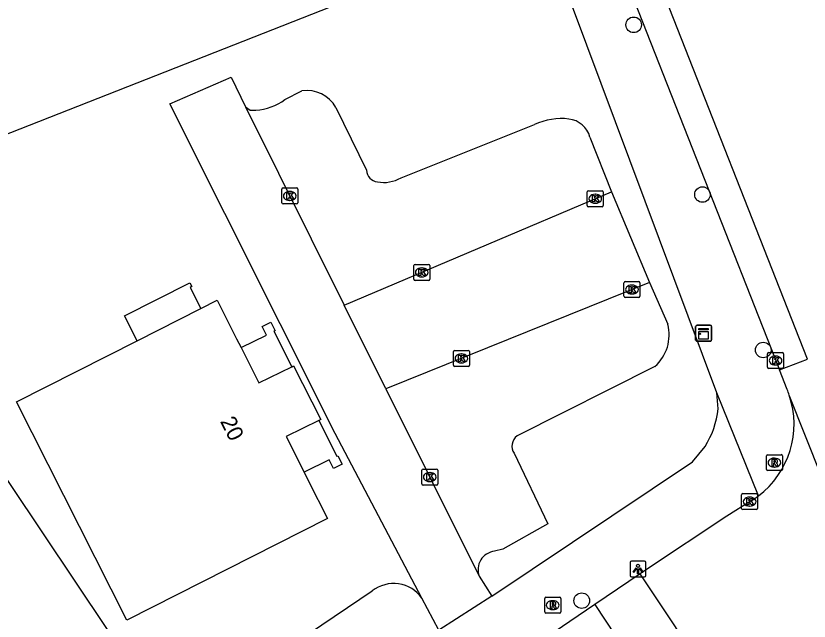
# Model space of a CAD drawing. Extents: x 161087 to 161922, y 382574 to 383873.
# Drawn here: x 161691.15 to 161740.93, y 382709.04 to 382747.01 of the extents above; entities that cross this region are included whole.
import ezdxf

# ---------------------------------------------------------------- set-up
doc = ezdxf.new("R2010")
doc.units = 0
for name, color, linetype in [('IMGEO_Boom', 7, 'Continuous'), ('IMGEO_Kast', 7, 'Continuous'), ('IMGEO_Kolk', 7, 'Continuous'), ('IMGEO_Lichtpunt', 7, 'Continuous'), ('IMGEO_Pand', 7, 'Continuous'), ('IMGEO_Pand_nummerreeks', 7, 'Continuous'), ('IMGEO_Parkeervlak_open', 7, 'Continuous'), ('IMGEO_Rijbaan_lokaal_open', 7, 'Continuous'), ('IMGEO_Rioolput', 7, 'Continuous'), ('IMGEO_Voetpad_op_trap', 7, 'Continuous'), ('IMGEO_Voetpad_open', 7, 'Continuous')]:
    doc.layers.add(name, color=color, linetype=linetype)

msp = doc.modelspace()

# ---------------------------------------------------------------- linework, layer by layer
at = {"layer": 'IMGEO_Boom'}
for centre in [(161729.923, 382746.451), (161734.24, 382735.804), (161738.053, 382726.048), (161726.662, 382710.319)]:
    msp.add_circle(centre, 0.489, dxfattribs=at)
at = {"layer": 'IMGEO_Kast'}
for p, q in [((161733.813, 382726.675), (161733.813, 382727.516)), ((161733.813, 382727.516), (161733.813, 382726.675)), ((161733.888, 382727.6), (161734.729, 382727.6)), ((161734.729, 382727.6), (161733.888, 382727.6)), ((161734.813, 382727.525), (161734.813, 382726.684)), ((161734.813, 382726.684), (161734.813, 382727.525)), ((161734.738, 382726.6), (161733.897, 382726.6)), ((161733.897, 382726.6), (161734.738, 382726.6))]:
    msp.add_line(p, q, dxfattribs=at)
for points in [[(161734.008, 382727.39), (161734.608, 382727.39), (161734.608, 382727.305), (161734.008, 382727.305), (161734.008, 382727.39)], [(161734.008, 382727.215), (161734.608, 382727.215), (161734.608, 382726.726), (161734.008, 382726.726), (161734.008, 382727.215)]]:
    msp.add_lwpolyline(points, dxfattribs=at)
msp.add_circle((161734.092, 382727.064), 0.0377, dxfattribs=at)
for centre, start, end in [((161733.891, 382727.522), 92.4484, 184.2845), ((161733.891, 382727.522), 92.4484, 184.2845), ((161734.735, 382727.522), 2.4484, 94.2845), ((161734.735, 382727.522), 2.4484, 94.2845), ((161733.891, 382726.678), 182.4484, 274.2845), ((161733.891, 382726.678), 182.4484, 274.2845), ((161734.735, 382726.678), 272.4484, 4.2845), ((161734.735, 382726.678), 272.4484, 4.2845)]:
    msp.add_arc(centre, 0.0779, start, end, dxfattribs=at)
at = {"layer": 'IMGEO_Kolk'}
for p, q in [((161707.915, 382736.214), (161708.767, 382736.214)), ((161707.84, 382735.288), (161707.84, 382736.14)), ((161708.328, 382735.994), (161708.353, 382735.994)), ((161708.841, 382736.14), (161708.841, 382735.288)), ((161727.01, 382735.111), (161727.01, 382735.963)), ((161727.085, 382736.037), (161727.937, 382736.037)), ((161727.498, 382735.817), (161727.523, 382735.817)), ((161728.011, 382735.963), (161728.011, 382735.111)), ((161708.767, 382735.214), (161707.915, 382735.214)), ((161708.351, 382735.434), (161708.326, 382735.434)), ((161727.521, 382735.257), (161727.496, 382735.257)), ((161727.937, 382735.037), (161727.085, 382735.037)), ((161716.125, 382730.492), (161716.125, 382731.344)), ((161716.2, 382731.418), (161717.052, 382731.418)), ((161716.613, 382731.198), (161716.638, 382731.198)), ((161717.126, 382731.344), (161717.126, 382730.492)), ((161717.052, 382730.418), (161716.2, 382730.418)), ((161716.636, 382730.638), (161716.611, 382730.638)), ((161729.315, 382729.417), (161729.315, 382730.269)), ((161729.39, 382730.343), (161730.242, 382730.343)), ((161730.316, 382730.269), (161730.316, 382729.417)), ((161729.803, 382730.123), (161729.828, 382730.123)), ((161730.242, 382729.343), (161729.39, 382729.343)), ((161729.826, 382729.563), (161729.801, 382729.563)), ((161718.61, 382725.093), (161718.61, 382725.945)), ((161718.685, 382726.019), (161719.537, 382726.019)), ((161719.098, 382725.799), (161719.123, 382725.799)), ((161719.611, 382725.945), (161719.611, 382725.093)), ((161738.328, 382724.961), (161738.328, 382725.813)), ((161738.403, 382725.887), (161739.255, 382725.887)), ((161739.329, 382725.813), (161739.329, 382724.961)), ((161719.121, 382725.239), (161719.096, 382725.239)), ((161738.816, 382725.667), (161738.841, 382725.667)), ((161719.537, 382725.019), (161718.685, 382725.019)), ((161739.255, 382724.887), (161738.403, 382724.887)), ((161738.839, 382725.107), (161738.814, 382725.107)), ((161716.627, 382717.65), (161716.627, 382718.502)), ((161716.702, 382718.576), (161717.554, 382718.576)), ((161717.115, 382718.356), (161717.14, 382718.356)), ((161717.628, 382718.502), (161717.628, 382717.65)), ((161717.138, 382717.796), (161717.113, 382717.796)), ((161717.554, 382717.576), (161716.702, 382717.576)), ((161736.698, 382716.109), (161736.698, 382716.961)), ((161736.773, 382717.035), (161737.625, 382717.035)), ((161737.186, 382716.815), (161737.211, 382716.815)), ((161737.699, 382716.961), (161737.699, 382716.109)), ((161737.209, 382716.255), (161737.184, 382716.255)), ((161737.625, 382716.035), (161736.773, 382716.035))]:
    msp.add_line(p, q, dxfattribs=at)
for points in [[(161707.915, 382736.214), (161708.767, 382736.214)], [(161707.84, 382735.288), (161707.84, 382736.14)], [(161708.161, 382735.914), (161708.284, 382735.914), (161708.284, 382735.763), (161708.414, 382735.914), (161708.578, 382735.914), (161708.432, 382735.763), (161708.585, 382735.514), (161708.433, 382735.514), (161708.348, 382735.678), (161708.284, 382735.611), (161708.284, 382735.514), (161708.161, 382735.514), (161708.161, 382735.914)], [(161708.841, 382736.14), (161708.841, 382735.288)], [(161727.01, 382735.111), (161727.01, 382735.963)], [(161727.085, 382736.037), (161727.937, 382736.037)], [(161727.331, 382735.737), (161727.454, 382735.737), (161727.454, 382735.586), (161727.584, 382735.737), (161727.748, 382735.737), (161727.602, 382735.586), (161727.755, 382735.337), (161727.603, 382735.337), (161727.518, 382735.501), (161727.454, 382735.434), (161727.454, 382735.337), (161727.331, 382735.337), (161727.331, 382735.737)], [(161728.011, 382735.963), (161728.011, 382735.111)], [(161708.767, 382735.214), (161707.915, 382735.214)], [(161727.937, 382735.037), (161727.085, 382735.037)], [(161716.125, 382730.492), (161716.125, 382731.344)], [(161716.2, 382731.418), (161717.052, 382731.418)], [(161717.126, 382731.344), (161717.126, 382730.492)], [(161716.446, 382731.118), (161716.569, 382731.118), (161716.569, 382730.967), (161716.699, 382731.118), (161716.863, 382731.118), (161716.717, 382730.967), (161716.87, 382730.718), (161716.718, 382730.718), (161716.633, 382730.882), (161716.569, 382730.815), (161716.569, 382730.718), (161716.446, 382730.718), (161716.446, 382731.118)], [(161717.052, 382730.418), (161716.2, 382730.418)], [(161729.315, 382729.417), (161729.315, 382730.269)], [(161729.39, 382730.343), (161730.242, 382730.343)], [(161730.316, 382730.269), (161730.316, 382729.417)], [(161729.636, 382730.043), (161729.759, 382730.043), (161729.759, 382729.892), (161729.889, 382730.043), (161730.053, 382730.043), (161729.907, 382729.892), (161730.06, 382729.643), (161729.908, 382729.643), (161729.823, 382729.807), (161729.759, 382729.74), (161729.759, 382729.643), (161729.636, 382729.643), (161729.636, 382730.043)], [(161730.242, 382729.343), (161729.39, 382729.343)], [(161718.61, 382725.093), (161718.61, 382725.945)], [(161718.685, 382726.019), (161719.537, 382726.019)], [(161718.931, 382725.719), (161719.054, 382725.719), (161719.054, 382725.568), (161719.184, 382725.719), (161719.348, 382725.719), (161719.202, 382725.568), (161719.355, 382725.319), (161719.203, 382725.319), (161719.118, 382725.483), (161719.054, 382725.416), (161719.054, 382725.319), (161718.931, 382725.319), (161718.931, 382725.719)], [(161719.611, 382725.945), (161719.611, 382725.093)], [(161738.328, 382724.961), (161738.328, 382725.813)], [(161738.403, 382725.887), (161739.255, 382725.887)], [(161739.329, 382725.813), (161739.329, 382724.961)], [(161738.649, 382725.587), (161738.772, 382725.587), (161738.772, 382725.436), (161738.902, 382725.587), (161739.066, 382725.587), (161738.92, 382725.436), (161739.073, 382725.187), (161738.921, 382725.187), (161738.836, 382725.351), (161738.772, 382725.284), (161738.772, 382725.187), (161738.649, 382725.187), (161738.649, 382725.587)], [(161719.537, 382725.019), (161718.685, 382725.019)], [(161739.255, 382724.887), (161738.403, 382724.887)], [(161716.627, 382717.65), (161716.627, 382718.502)], [(161716.702, 382718.576), (161717.554, 382718.576)], [(161716.948, 382718.276), (161717.071, 382718.276), (161717.071, 382718.125), (161717.201, 382718.276), (161717.365, 382718.276), (161717.219, 382718.125), (161717.372, 382717.876), (161717.22, 382717.876), (161717.135, 382718.04), (161717.071, 382717.973), (161717.071, 382717.876), (161716.948, 382717.876), (161716.948, 382718.276)], [(161717.628, 382718.502), (161717.628, 382717.65)], [(161717.554, 382717.576), (161716.702, 382717.576)], [(161736.698, 382716.109), (161736.698, 382716.961)], [(161736.773, 382717.035), (161737.625, 382717.035)], [(161737.699, 382716.961), (161737.699, 382716.109)], [(161737.019, 382716.735), (161737.142, 382716.735), (161737.142, 382716.584), (161737.272, 382716.735), (161737.436, 382716.735), (161737.29, 382716.584), (161737.443, 382716.335), (161737.291, 382716.335), (161737.206, 382716.499), (161737.142, 382716.432), (161737.142, 382716.335), (161737.019, 382716.335), (161737.019, 382716.735)], [(161737.625, 382716.035), (161736.773, 382716.035)]]:
    msp.add_lwpolyline(points, dxfattribs=at)
for centre, start, end in [((161707.917, 382736.138), 91.552, 178.448), ((161707.917, 382736.138), 91.552, 178.448), ((161708.765, 382736.138), 1.552, 88.448), ((161708.765, 382736.138), 1.552, 88.448), ((161727.087, 382735.961), 91.552, 178.448), ((161727.087, 382735.961), 91.552, 178.448), ((161727.935, 382735.961), 1.552, 88.448), ((161727.935, 382735.961), 1.552, 88.448), ((161707.917, 382735.29), 181.552, 268.448), ((161707.917, 382735.29), 181.552, 268.448), ((161708.765, 382735.29), 271.552, 358.448), ((161708.765, 382735.29), 271.552, 358.448), ((161727.087, 382735.113), 181.552, 268.448), ((161727.087, 382735.113), 181.552, 268.448), ((161727.935, 382735.113), 271.552, 358.448), ((161727.935, 382735.113), 271.552, 358.448), ((161716.202, 382731.342), 91.552, 178.448), ((161716.202, 382731.342), 91.552, 178.448), ((161717.05, 382731.342), 1.552, 88.448), ((161717.05, 382731.342), 1.552, 88.448), ((161716.202, 382730.494), 181.552, 268.448), ((161716.202, 382730.494), 181.552, 268.448), ((161717.05, 382730.494), 271.552, 358.448), ((161717.05, 382730.494), 271.552, 358.448), ((161729.392, 382730.267), 91.552, 178.448), ((161729.392, 382730.267), 91.552, 178.448), ((161730.24, 382730.267), 1.552, 88.448), ((161730.24, 382730.267), 1.552, 88.448), ((161729.392, 382729.419), 181.552, 268.448), ((161729.392, 382729.419), 181.552, 268.448), ((161730.24, 382729.419), 271.552, 358.448), ((161730.24, 382729.419), 271.552, 358.448), ((161718.687, 382725.943), 91.552, 178.448), ((161718.687, 382725.943), 91.552, 178.448), ((161719.535, 382725.943), 1.552, 88.448), ((161719.535, 382725.943), 1.552, 88.448), ((161738.405, 382725.811), 91.552, 178.448), ((161738.405, 382725.811), 91.552, 178.448), ((161739.253, 382725.811), 1.552, 88.448), ((161739.253, 382725.811), 1.552, 88.448), ((161718.687, 382725.095), 181.552, 268.448), ((161718.687, 382725.095), 181.552, 268.448), ((161719.535, 382725.095), 271.552, 358.448), ((161719.535, 382725.095), 271.552, 358.448), ((161738.405, 382724.963), 181.552, 268.448), ((161738.405, 382724.963), 181.552, 268.448), ((161739.253, 382724.963), 271.552, 358.448), ((161739.253, 382724.963), 271.552, 358.448), ((161716.704, 382718.5), 91.552, 178.448), ((161716.704, 382718.5), 91.552, 178.448), ((161717.552, 382718.5), 1.552, 88.448), ((161717.552, 382718.5), 1.552, 88.448), ((161716.704, 382717.652), 181.552, 268.448), ((161716.704, 382717.652), 181.552, 268.448), ((161717.552, 382717.652), 271.552, 358.448), ((161717.552, 382717.652), 271.552, 358.448), ((161736.775, 382716.959), 91.552, 178.448), ((161736.775, 382716.959), 91.552, 178.448), ((161737.623, 382716.959), 1.552, 88.448), ((161737.623, 382716.959), 1.552, 88.448), ((161736.775, 382716.111), 181.552, 268.448), ((161736.775, 382716.111), 181.552, 268.448), ((161737.623, 382716.111), 271.552, 358.448), ((161737.623, 382716.111), 271.552, 358.448)]:
    msp.add_arc(centre, 0.0765, start, end, dxfattribs=at)
for centre, major_axis, ratio, start_param, end_param in [((161708.327, 382735.714), (-0.387, 0.002), 0.722429, 4.712389, 7.853982), ((161708.352, 382735.714), (-0.39, 0.002), 0.717154, 1.570796, 4.712389), ((161727.497, 382735.537), (-0.387, 0.002), 0.722429, 4.712389, 7.853982), ((161727.522, 382735.537), (-0.39, 0.002), 0.717154, 1.570796, 4.712389), ((161716.612, 382730.918), (-0.387, 0.002), 0.722429, 4.712389, 7.853982), ((161716.637, 382730.918), (-0.39, 0.002), 0.717154, 1.570796, 4.712389), ((161729.802, 382729.843), (-0.387, 0.002), 0.722429, 4.712389, 7.853982), ((161729.827, 382729.843), (-0.39, 0.002), 0.717154, 1.570796, 4.712389), ((161719.097, 382725.519), (-0.387, 0.002), 0.722429, 4.712389, 7.853982), ((161719.122, 382725.519), (-0.39, 0.002), 0.717154, 1.570796, 4.712389), ((161738.815, 382725.387), (-0.387, 0.002), 0.722429, 4.712389, 7.853982), ((161738.84, 382725.387), (-0.39, 0.002), 0.717154, 1.570796, 4.712389), ((161717.114, 382718.076), (-0.387, 0.002), 0.722429, 4.712389, 7.853982), ((161717.139, 382718.076), (-0.39, 0.002), 0.717154, 1.570796, 4.712389), ((161737.185, 382716.535), (-0.387, 0.002), 0.722429, 4.712389, 7.853982), ((161737.21, 382716.535), (-0.39, 0.002), 0.717154, 1.570796, 4.712389)]:
    msp.add_ellipse(centre, major_axis=major_axis, ratio=ratio, start_param=start_param, end_param=end_param, dxfattribs=at)
at = {"layer": 'IMGEO_Lichtpunt'}
for p, q in [((161730.598, 382712.804), (161729.79, 382712.804)), ((161730.598, 382712.804), (161729.79, 382712.804)), ((161729.696, 382712.709), (161729.696, 382711.902)), ((161729.696, 382712.709), (161729.696, 382711.902)), ((161730.692, 382711.902), (161730.692, 382712.709)), ((161730.692, 382711.902), (161730.692, 382712.709)), ((161729.79, 382711.808), (161730.598, 382711.808)), ((161729.79, 382711.808), (161730.598, 382711.808))]:
    msp.add_line(p, q, dxfattribs=at)
for points in [[(161730.07, 382712.373), (161730.109, 382712.345), (161729.921, 382712.083), (161729.883, 382712.11), (161730.07, 382712.373)], [(161730.172, 382712.325), (161730.219, 382712.325), (161730.219, 382712.003), (161730.172, 382712.003), (161730.172, 382712.325)], [(161730.282, 382712.345), (161730.32, 382712.372), (161730.507, 382712.11), (161730.468, 382712.082), (161730.282, 382712.345)]]:
    msp.add_lwpolyline(points, dxfattribs=at)
msp.add_circle((161730.195, 382712.507), 0.0994, dxfattribs=at)
for centre, start, end in [((161729.79, 382712.709), 90, 180), ((161729.79, 382712.709), 90, 180), ((161730.598, 382712.709), 0, 90), ((161730.598, 382712.709), 0, 90), ((161729.79, 382711.902), 180, 270), ((161729.79, 382711.902), 180, 270), ((161730.598, 382711.902), 270, 0), ((161730.598, 382711.902), 270, 360)]:
    msp.add_arc(centre, 0.0946, start, end, dxfattribs=at)
at = {"layer": 'IMGEO_Pand'}
for points in [[(161724.119, 382752.784), (161717.042, 382750), (161681.588, 382736.054), (161680.528, 382738.609), (161673.543, 382741.713), (161674.844, 382744.75), (161674.327, 382746.063), (161678.977, 382747.902), (161684.281, 382750), (161709.293, 382759.894), (161707.998, 382763.215), (161708.322, 382763.343), (161713.734, 382765.484), (161718.383, 382767.322)], [(161702.757, 382728.648), (161703.783, 382729.167), (161705.006, 382726.749), (161705.285, 382726.198)], [(161698.759, 382726.627), (161702.757, 382728.648)], [(161709.236, 382718.381), (161709.52, 382717.82), (161710.707, 382715.472), (161698.109, 382709.102), (161691.184, 382722.797), (161698.759, 382726.627)], [(161705.285, 382726.198), (161706.404, 382723.984), (161708.461, 382724.998)], [(161708.461, 382724.998), (161708.577, 382725.055), (161710.283, 382721.682), (161710.166, 382721.624)], [(161710.166, 382721.624), (161708.109, 382720.611), (161709.236, 382718.381)]]:
    msp.add_lwpolyline(points, dxfattribs=at)
at = {"layer": 'IMGEO_Parkeervlak_open'}
for points in [[(161716.628, 382710.484), (161711.193, 382720.807), (161700.803, 382741.504), (161704.669, 382743.166), (161705.551, 382741.315)], [(161708.038, 382741.762), (161709.101, 382742.314)], [(161705.551, 382741.315), (161705.844, 382741.092), (161706.21, 382741.098)], [(161705.551, 382741.315), (161711.76, 382728.852)], [(161711.235, 382741.262), (161713.156, 382737.323)], [(161715.325, 382736.845), (161723.704, 382740.189)], [(161727.181, 382739.412), (161728.536, 382735.971)], [(161711.76, 382728.852), (161728.536, 382735.971)], [(161728.536, 382735.971), (161730.921, 382730.29)], [(161730.921, 382730.29), (161714.374, 382723.606)], [(161730.921, 382730.29), (161732.058, 382727.66)], [(161714.374, 382723.606), (161711.76, 382728.852)], [(161731.251, 382725.02), (161722.612, 382720.655)], [(161714.374, 382723.606), (161720.227, 382711.859)], [(161722.413, 382719.565), (161724.533, 382715.135), (161721.719, 382713.546), (161721.191, 382713.416)], [(161720.227, 382711.859), (161721.016, 382710.607)]]:
    msp.add_lwpolyline(points, dxfattribs=at)
for centre, radius, start, end in [((161709.384, 382740.198), 2.134, 29.8858, 97.6303), ((161705.972, 382744.602), 3.512, 273.8903, 306.0357), ((161725.383, 382736.686), 3.885, 82.9194, 115.6089), ((161725.668, 382738.979), 1.574, 15.968, 82.9082), ((161713.955, 382737.387), 0.802, 184.5842, 261.4323), ((161714.225, 382738.829), 2.269, 260.1323, 299.0045), ((161729.562, 382726.98), 2.587, 310.7538, 15.2513), ((161723.09, 382720.005), 0.807, 126.3076, 212.9994), ((161721.311, 382712.265), 1.158, 95.9641, 200.5093)]:
    msp.add_arc(centre, radius, start, end, dxfattribs=at)
at = {"layer": 'IMGEO_Rijbaan_lokaal_open'}
for points in [[(161739.064, 382724.796), (161740.835, 382725.464), (161731.19, 382750), (161725.722, 382763.908)], [(161682.663, 382729.735), (161700.929, 382702.454)], [(161739.551, 382723.574), (161739.064, 382724.796)], [(161746.805, 382705.307), (161739.688, 382723.21)], [(161737.293, 382716.577), (161735.771, 382715.63), (161730.733, 382712.274), (161730.322, 382711.996)], [(161730.322, 382711.996), (161727.49, 382710.077)], [(161734.831, 382705.246), (161730.322, 382711.996)], [(161727.49, 382710.077), (161723.893, 382707.64), (161723.499, 382707.38)], [(161727.49, 382710.077), (161731.947, 382703.33)]]:
    msp.add_lwpolyline(points, dxfattribs=at)
for centre, radius, start, end in [((161734.743, 382721.557), 5.214, 18.4874, 22.7626), ((161734.328, 382721.397), 5.658, 307.1736, 18.691), ((161734.375, 382721.324), 5.572, 301.5814, 307.2426)]:
    msp.add_arc(centre, radius, start, end, dxfattribs=at)
at = {"layer": 'IMGEO_Rioolput'}
for p, q in [((161738.256, 382718.555), (161738.256, 382719.407)), ((161738.331, 382719.481), (161739.183, 382719.481)), ((161738.744, 382719.261), (161738.769, 382719.261)), ((161739.257, 382719.407), (161739.257, 382718.555)), ((161739.183, 382718.481), (161738.331, 382718.481)), ((161738.767, 382718.701), (161738.742, 382718.701)), ((161724.341, 382709.614), (161724.341, 382710.466)), ((161724.416, 382710.54), (161725.268, 382710.54)), ((161724.829, 382710.32), (161724.854, 382710.32)), ((161725.342, 382710.466), (161725.342, 382709.614)), ((161725.268, 382709.54), (161724.416, 382709.54)), ((161724.852, 382709.76), (161724.827, 382709.76))]:
    msp.add_line(p, q, dxfattribs=at)
for points in [[(161738.256, 382718.555), (161738.256, 382719.407)], [(161738.331, 382719.481), (161739.183, 382719.481)], [(161739.257, 382719.407), (161739.257, 382718.555)], [(161738.845, 382719.179), (161738.593, 382719.181), (161738.593, 382718.781)], [(161738.593, 382718.781), (161738.717, 382718.781), (161738.717, 382718.943), (161738.728, 382718.943)], [(161738.771, 382719.1), (161738.717, 382719.1), (161738.717, 382719.019)], [(161738.717, 382719.019), (161738.769, 382719.019)], [(161738.775, 382718.914), (161738.846, 382718.781), (161738.986, 382718.781), (161738.921, 382718.907)], [(161739.183, 382718.481), (161738.331, 382718.481)], [(161724.341, 382709.614), (161724.341, 382710.466)], [(161724.416, 382710.54), (161725.268, 382710.54)], [(161725.342, 382710.466), (161725.342, 382709.614)], [(161724.93, 382710.238), (161724.678, 382710.24), (161724.678, 382709.84)], [(161724.678, 382709.84), (161724.802, 382709.84), (161724.802, 382710.002), (161724.813, 382710.002)], [(161724.856, 382710.159), (161724.802, 382710.159), (161724.802, 382710.078)], [(161724.802, 382710.078), (161724.854, 382710.078)], [(161724.86, 382709.973), (161724.931, 382709.84), (161725.071, 382709.84), (161725.006, 382709.966)], [(161725.268, 382709.54), (161724.416, 382709.54)]]:
    msp.add_lwpolyline(points, dxfattribs=at)
for centre, radius, start, end in [((161738.333, 382719.405), 0.0765, 91.552, 178.448), ((161738.333, 382719.405), 0.0765, 91.552, 178.448), ((161739.181, 382719.405), 0.0765, 1.552, 88.448), ((161739.181, 382719.405), 0.0765, 1.552, 88.448), ((161738.727, 382718.89), 0.0533, 26.0293, 88.6989), ((161738.753, 382719.208), 0.19, 274.7715, 282.9687), ((161738.777, 382719.004), 0.0964, 77.0061, 93.1865), ((161738.791, 382719.061), 0.0378, 276.6634, 79.6772), ((161738.844, 382719.069), 0.109, 350.3612, 89.416), ((161738.842, 382719.069), 0.112, 277.5842, 350.9817), ((161738.826, 382718.854), 0.108, 29.5134, 73.7905), ((161738.333, 382718.557), 0.0765, 181.552, 268.448), ((161738.333, 382718.557), 0.0765, 181.552, 268.448), ((161739.181, 382718.557), 0.0765, 271.552, 358.448), ((161739.181, 382718.557), 0.0765, 271.552, 358.448), ((161724.418, 382710.464), 0.0765, 91.552, 178.448), ((161724.418, 382710.464), 0.0765, 91.552, 178.448), ((161725.266, 382710.464), 0.0765, 1.552, 88.448), ((161725.266, 382710.464), 0.0765, 1.552, 88.448), ((161724.812, 382709.949), 0.0533, 26.0293, 88.6989), ((161724.838, 382710.267), 0.19, 274.7715, 282.9687), ((161724.862, 382710.063), 0.0964, 77.0061, 93.1865), ((161724.876, 382710.12), 0.0378, 276.6634, 79.6772), ((161724.929, 382710.128), 0.109, 350.3612, 89.416), ((161724.927, 382710.128), 0.112, 277.5842, 350.9817), ((161724.911, 382709.913), 0.108, 29.5134, 73.7905), ((161724.418, 382709.616), 0.0765, 181.552, 268.448), ((161724.418, 382709.616), 0.0765, 181.552, 268.448), ((161725.266, 382709.616), 0.0765, 271.552, 358.448), ((161725.266, 382709.616), 0.0765, 271.552, 358.448)]:
    msp.add_arc(centre, radius, start, end, dxfattribs=at)
for centre, major_axis, ratio, start_param, end_param in [((161738.743, 382718.981), (-0.387, 0.002), 0.722429, 4.712389, 7.853982), ((161738.768, 382718.981), (-0.39, 0.002), 0.717154, 1.570796, 4.712389), ((161724.828, 382710.04), (-0.387, 0.002), 0.722429, 4.712389, 7.853982), ((161724.853, 382710.04), (-0.39, 0.002), 0.717154, 1.570796, 4.712389)]:
    msp.add_ellipse(centre, major_axis=major_axis, ratio=ratio, start_param=start_param, end_param=end_param, dxfattribs=at)
at = {"layer": 'IMGEO_Voetpad_op_trap'}
for points in [[(161698.759, 382726.627), (161697.969, 382728.188), (161702.074, 382730.264), (161702.192, 382730.032), (161702.084, 382729.978), (161702.757, 382728.648)], [(161705.285, 382726.198), (161706.884, 382726.985), (161706.609, 382727.53), (161707.147, 382727.795), (161707.418, 382727.26), (161707.337, 382727.22), (161708.461, 382724.998)], [(161710.166, 382721.624), (161711.299, 382719.384), (161711.353, 382719.411), (161711.623, 382718.875), (161711.085, 382718.61), (161710.814, 382719.159), (161709.236, 382718.381)]]:
    msp.add_lwpolyline(points, dxfattribs=at)
at = {"layer": 'IMGEO_Voetpad_open'}
for points in [[(161724.135, 382762.816), (161729.167, 382750), (161739.064, 382724.796)], [(161735.149, 382723.363), (161725.188, 382750), (161724.859, 382750.879), (161724.119, 382752.784)], [(161735.231, 382722.357), (161735.149, 382723.363)], [(161737.747, 382716.888), (161735.149, 382723.363)], [(161721.016, 382710.607), (161733.604, 382719.024), (161734.405, 382719.996)], [(161700.929, 382702.454), (161713.52, 382710.932)], [(161721.016, 382710.607), (161717.704, 382708.463), (161716.628, 382710.484)]]:
    msp.add_lwpolyline(points, dxfattribs=at)
for centre, radius, start, end in [((161729.645, 382722.986), 5.621, 327.8623, 353.5728), ((161714.86, 382709.225), 2.17, 35.4615, 128.1338)]:
    msp.add_arc(centre, radius, start, end, dxfattribs=at)

# ---------------------------------------------------------------- texts
at = {"layer": 'IMGEO_Pand_nummerreeks'}
msp.add_text('20', height=1, rotation=296.8199, dxfattribs=at).set_placement((161703.947, 382721.575))

doc.saveas('drawing.dxf')
